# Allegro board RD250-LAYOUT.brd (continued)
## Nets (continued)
SIG007121: R301.2 R302.1
SIG007122: R302.2 R303.1
SIG007123: C302.2 D302.C D305.C DP301.1 IC301.5 R304.2 R305.2 R307.1
SIG007124: IC302.4 Q301.G R314.1 R315.2
SIG007125: Q302.D Q303.G R318.1 R319.2
SIG007126: D305.A R320.1 R321.2
SIG007127: D306.A R322.1 R323.2
SIGN254: D66.A R66.1
SIGN255: D61.A R58.1
SIGN266: C81.2 DP55.1 L54.2 Q52.G R64.2
SIGN267: C82.2 DP53.1 L53.2 Q51.G R56.2
SS/EN: C251.2 IC251.5 R252.2 R353.2
VREF_PSFB: C254.2 IC251.1 R263.2 R265.2 R268.2 R270.2 R272.2 R279.2

Pads without a net: CN2 2; CN102 1; CN105 1; D104 NC; D107 NC; D113 NC; D116 NC; D405 NC; IC1 1 4 5 8; IC101 7 12 13; IC102 7 12 13; IC151 1 8; IC201 1 8; IC251 16; IC304 7 10; IC403 4; IC451 4; T101 4 6 7; T151 1 3 4 6 7 8 9 10 11 12; T201 1 3 4 6 7 8 9 10 11 12; T401 2 7 10 11 14

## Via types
v1: diameter 7, hole 3.2, TOP to BOTTOM, 4 vias
v2: diameter 0.55, hole 0.3, TOP to BOTTOM, 659 vias

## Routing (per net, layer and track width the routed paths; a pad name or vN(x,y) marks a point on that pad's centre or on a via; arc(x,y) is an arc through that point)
P48V: length 44.3
  CONDUCTIVE3 w0.3: CN503.1 292.18,30.38 CN501.3
  CONDUCTIVE4 w0.5: CN501.4 299.15,24.7 299.15,11.3 v2(301.45,9)
  BOTTOM w0.5: C511.2 316.4,26.25 ; C511.2 317.75,25.25 ; C511.2 C510.2 ; C510.2 313.9,26.45 ; C510.2 312.35,25.25
VCC5R0_1: length 199.5
  TOP w0.3: 147.15,106.61 v2(147.15,105.25) 147.75,104.65 151.2,104.65 152.53,105.98 IC101.8 ; 184.31,60.39 184.31,61.75 ; 184.31,61.75 v2(182.8,61.75) ; 184.31,61.75 C413.2
  TOP w0.825: IC403.5 184.31,60.39
  TOP w0.92: 147.15,106.61 C104.2
  CONDUCTIVE3 w0.3: v2(220.4,11.9) 218.25,11.9 213.4,7.05 209.18,7.05 209.08,7.02 209.04,6.99 208.1,6.05 195.25,6.05 190.9,10.4 190.9,53.65 v2(182.8,61.75)
  CONDUCTIVE4 w0.3: v2(147.15,105.25) 137.75,95.85 137.75,85.15 144.55,78.35 149,78.35 158.55,68.8 179.05,68.8 182.8,65.05 v2(182.8,61.75) 181.3,61.75 179.5,63.55 179.5,66.15 v2(177.65,68)
  BOTTOM w0.3: IC304.16 222.3,11.63 222.14,11.47 C309.2 220.82,11.47 v2(220.4,11.9)
  vias: v2(167.4,67.75) v2(173.3,67.55)
VCC5R0_2: length 4.7
  BOTTOM w0.3: 235.77,13.3 236.68,13.3 ; IC304.1 233.12,12.47 233.95,13.3 235.6,13.3
  BOTTOM w0.4: 235.6,13.3 235.77,13.3
VCC12R0_1: length 31.7
  TOP w0.3: v2(144.4,53.5) 143.85,53.5 143.26,52.91 143.26,52.04 ; 142,44.3 v2(143.1,44.3) ; 220.28,6.12 221.6,6.12
  TOP w0.45: R314.2 220.28,6.12 ; 141.82,44.3 142,44.3
  TOP w0.825: IC51.8 143.26,52.04
  CONDUCTIVE4 w0.3: v2(122.5,3.4) 130.42,3.4 130.52,3.43 130.56,3.46 v2(133.6,6.5)
  BOTTOM w0.3: RY1.4 97.2,70.88 97.17,70.98 97.14,71.02 95.67,72.49 95.58,72.54 95.53,72.55 D1.C ; 206.28,6.4 204.62,4.75 v2(202.9,4.75) v2(202.1,4.75) ; 97.12,65.91 C11.2
  BOTTOM w0.45: R4.1 97.12,65.91
  vias: v2(149.25,103.5) v2(153.3,43.9) v2(184.3,52.55) v2(184.3,51.85)
VCC12R0_2:
  vias: v2(243.15,123.55) v2(243.15,85.45) v2(243.95,123.55) v2(243.95,85.45) v2(248.8,13.5) v2(258.65,28.7) v2(258.65,27.9) v2(258.65,27.1) v2(259.45,28.7) v2(259.45,27.9) v2(259.45,27.1)
ACIN: length 16.2
  BOTTOM w0.3: 122,17.43 122,19.37 121.97,19.47 121.94,19.52 120.04,21.42 119.95,21.47 119.9,21.48 R301.1 ; 113.89,21.48 110.47,21.48 110.37,21.45 110.32,21.42 D51.C
  BOTTOM w0.92: R301.1 113.89,21.48 ; C301.2 122,17.43
CONN002: length 7.9
  TOP w0.3: 150.78,90.48 150.78,91.4 ; 145.72,86 150.02,90.3 150.78,90.3
  TOP w0.45: 150.78,90.3 150.78,90.48
  vias: v2(166.15,76.15) v2(166.85,76.15)
CONN004: length 222.9
  TOP w0.3: 285.81,37.01 284.76,37.01 284.3,36.55 283.5,36.55 283,37.05 283,41.15 284.75,42.9 287.65,42.9 288.1,42.45 C509.2 ; 288.21,41.5 v2(289.6,41.5) ; 288.1,41.03 288.1,39.19
  TOP w0.8: 288.1,41.03 C509.2 288.21,41.5
  TOP w0.825: IC501.3 285.81,37.01
  CONDUCTIVE3 w0.3: v2(305.75,47.6) 305.75,48.25 305.35,48.65 296.75,48.65 v2(289.6,41.5)
  CONDUCTIVE3 w0.5: v2(267.5,14.1) 271.1,14.1 296.8,39.8 296.8,45.15 299.25,47.6 v2(305.75,47.6)
  CONDUCTIVE3 w1.5: C501.2 285.1,125.7 ; C501.2 287.3,126.95 ; C501.2 289.5,125.7 ; C501.2 287.3,123.5 ; C505.2 299.7,76.4 ; C505.2 299.7,79.85 ; C505.2 297.5,78.6 ; C505.2 301.9,78.6 ; C503.2 306.5,67.95 ; C503.2 308.7,65.75 ; C503.2 308.7,70.15 ; C503.2 310.9,67.95 ; C504.2 287.3,76 ; C504.2 287.3,79.85 ; C504.2 289.5,78.6 ; C504.2 285.1,78.6 ; C502.2 301.9,125.7 ; C502.2 299.7,123.5 ; C502.2 299.7,126.95 ; C502.2 297.5,125.7
  CONDUCTIVE4 w1.5: C505.2 299.7,79.85 ; C505.2 299.7,76.4 ; C505.2 301.9,78.6 ; C505.2 297.5,78.6 ; C504.2 287.3,79.85 ; C504.2 289.5,78.6 ; C504.2 287.3,76.05 ; C504.2 285.1,78.6 ; C501.2 285.1,125.7 ; C501.2 289.5,125.7 ; C501.2 287.3,123.5 ; C501.2 287.3,126.95 ; C502.2 299.7,123.5 ; C502.2 301.9,125.7 ; C502.2 299.7,126.95 ; C502.2 297.5,125.7 ; C503.2 308.7,65.75 ; C503.2 310.9,67.95 ; C503.2 308.7,70.15 ; C503.2 306.5,67.95
  BOTTOM w0.3: 267.5,13.1 v2(267.5,14.1)
  BOTTOM w0.45: R287.2 267.5,13.1
  BOTTOM w0.5: 284,128.15 283.25,128.9 C507.2 ; C506.2 280.65,81.8 ; C506.2 283.3,81.8 ; C506.2 282,80.9 ; C507.2 282.3,127.75 ; C507.2 280.75,128.9
  BOTTOM w1.5: C502.2 299.7,126.95 ; C502.2 297.9,125.7 ; C502.2 301.7,125.7 ; C502.2 299.7,124 ; C505.2 301.9,78.6 ; C505.2 297.5,78.6 ; C505.2 299.7,79.8 ; C505.2 299.7,76.4 ; C501.2 287.3,126.95 ; C501.2 289.6,125.7 ; C501.2 287.3,123.65 ; C501.2 285.25,125.7 ; C504.2 287.3,79.85 ; C504.2 287.3,76.05 ; C504.2 285.1,78.6 ; C504.2 289.5,78.6 ; C503.2 308.7,66.25 ; C503.2 310.9,67.95 ; C503.2 306.5,67.95 ; C503.2 308.7,70.15
  vias: v2(279.65,127.3) v2(279.65,81.2) v2(280.45,127.3) v2(280.45,81.2) v2(297.2,116.8) v2(297.2,116.1) v2(297.2,115.4) v2(297.2,114.7) v2(297.2,114) v2(297.2,113.3) v2(297.2,112.6) v2(297.2,111.9) v2(297.2,111.2) v2(297.2,110.5) v2(297.2,69.7) v2(297.2,69) v2(297.2,68.3) v2(297.2,67.6) v2(297.2,66.9) v2(297.2,66.2) v2(297.2,65.5) v2(297.2,64.8) v2(297.2,64.1) v2(297.2,63.4) v2(297.2,53.5) v2(297.2,52.8) v2(297.2,52.1) v2(297.2,51.4) v2(297.2,50.7) v2(297.2,50) v2(297.9,116.8) v2(297.9,116.1) v2(297.9,115.4) v2(297.9,114.7) v2(297.9,114) v2(297.9,113.3) v2(297.9,112.6) v2(297.9,111.9) v2(297.9,111.2) v2(297.9,110.5) v2(297.9,69.7) v2(297.9,69) v2(297.9,68.3) v2(297.9,67.6) v2(297.9,66.9) v2(297.9,66.2) v2(297.9,65.5) v2(297.9,64.8) v2(297.9,64.1) v2(297.9,63.4) v2(297.9,53.5) v2(297.9,52.8) v2(297.9,52.1) v2(297.9,51.4) v2(297.9,50.7) v2(297.9,50) v2(298.6,116.8) v2(298.6,116.1) v2(298.6,115.4) v2(298.6,114.7) v2(298.6,114) v2(298.6,113.3) v2(298.6,112.6) v2(298.6,111.9) v2(298.6,111.2) v2(298.6,110.5) v2(298.6,69.7) v2(298.6,69) v2(298.6,68.3) v2(298.6,67.6) v2(298.6,66.9) v2(298.6,66.2) v2(298.6,65.5) v2(298.6,64.8) v2(298.6,64.1) v2(298.6,63.4) v2(298.6,53.5) v2(298.6,52.8) v2(298.6,52.1) v2(298.6,51.4) v2(298.6,50.7) v2(298.6,50) v2(299.3,116.8) v2(299.3,116.1) v2(299.3,115.4) v2(299.3,114.7) v2(299.3,114) v2(299.3,113.3) v2(299.3,112.6) v2(299.3,111.9) v2(299.3,111.2) v2(299.3,110.5) v2(299.3,69.7) v2(299.3,69) v2(299.3,68.3) v2(299.3,67.6) v2(299.3,66.9) v2(299.3,66.2) v2(299.3,65.5) v2(299.3,64.8) v2(299.3,64.1) v2(299.3,63.4) v2(299.3,53.5) v2(299.3,52.8) v2(299.3,52.1) v2(299.3,51.4) v2(299.3,50.7) v2(299.3,50) v2(300,116.8) v2(300,116.1) v2(300,115.4) v2(300,114.7) v2(300,114) v2(300,113.3) v2(300,112.6) v2(300,111.9) v2(300,111.2) v2(300,110.5) v2(300,69.7) v2(300,69) v2(300,68.3) v2(300,67.6) v2(300,66.9) v2(300,66.2) v2(300,65.5) v2(300,64.8) v2(300,64.1) v2(300,63.4) v2(300,53.5) v2(300,52.8) v2(300,52.1) v2(300,51.4) v2(300,50.7) v2(300,50) v2(300.7,116.8) v2(300.7,116.1) v2(300.7,115.4) v2(300.7,114.7) v2(300.7,114) v2(300.7,113.3) v2(300.7,112.6) v2(300.7,111.9) v2(300.7,111.2) v2(300.7,110.5) v2(300.7,69.7) v2(300.7,69) v2(300.7,68.3) v2(300.7,67.6) v2(300.7,66.9) v2(300.7,66.2) v2(300.7,65.5) v2(300.7,64.8) v2(300.7,64.1) v2(300.7,63.4) v2(300.7,53.5) v2(300.7,52.8) v2(300.7,52.1) v2(300.7,51.4) v2(300.7,50.7) v2(300.7,50)
CS: length 36.6
  TOP w0.3: v2(249.7,10.9) R284.2 ; 250.12,8.8 251.6,8.8
  TOP w0.83: R284.2 250.12,8.8
  CONDUCTIVE3 w0.5: v2(249.7,10.9) 247.05,13.55 v2(247.05,42.4)
CSA: length 129.7
  TOP w0.3: D62.C 140.68,45.2 140.97,44.9 140.97,44.48 ; v2(143.8,37.4) 140.97,40.23 140.97,44.12 ; DP52.1 155.6,3.8 155,4.4 v2(154.45,4.4)
  TOP w0.45: 140.97,44.48 R59.1 140.97,44.12
  CONDUCTIVE3 w0.3: v2(154.45,4.4) 153.75,5.1 153.75,8.35 152.7,9.4 152.7,35.25 150.55,37.4 v2(143.8,37.4) 141.8,37.4 137.5,41.7 121.55,41.7 112.8,50.45 112.8,76.75 114.7,78.65 v2(114.7,82.2)
  BOTTOM w0.3: 153.58,4.35 154.45,4.35 ; D58.C 116.62,84.53 116.3,84.2 R52.2 115.37,82.5 115.07,82.2 v2(114.7,82.2)
  BOTTOM w0.45: R68.1 153.58,4.35
CSB: length 104.1
  TOP w0.3: 155.3,43.9 D67.C ; R67.1 155.12,42.95 154.18,42 v2(150.15,42) ; v2(156.2,5.4) 157.72,5.4 157.77,5.39 157.86,5.34 DP54.1
  TOP w0.45: R67.1 155.3,43.9
  CONDUCTIVE3 w0.3: v2(156.2,5.4) 157.7,6.9 157.7,34.45 v2(150.15,42) 150.15,51.2 144.9,56.45 144.9,62.95 139.2,68.65 139.2,79.2 133.5,84.9 v2(131.9,84.9)
  BOTTOM w0.3: 155.38,5.4 v2(156.2,5.4)
  BOTTOM w0.45: R69.1 155.38,5.4
FG1:
  vias: v1(58.6,58)
FG2: length 5.5
  BOTTOM w0.3: 304.55,9.97 C513.2 303.45,9.25 ; 304.55,9.97 R506.1 ; 304.55,9.97 R505.1 304.55,9.25 ; R506.1 305.65,9.2 ; R506.1 306.75,9.97
  vias: v1(311.5,7)
HS1_1: length 6.9
  TOP w0.3: 80.88,129.53 87.6,129.53
  TOP w0.45: R422.2 80.88,129.53
HS1_2: length 10.1
  BOTTOM w0.5: R423.2 176.07,124.03 v1(170.6,129.5)
LGND: length 311.2
  TOP w0.3: 249.7,7.14 v2(249.7,5.75) 249.7,4.7 ; 249.7,3.6 249.7,4.53
  TOP w0.4: 249.7,4.53 249.7,4.7
  TOP w0.5: DP501.1 299.05,21.7 ; DP501.1 295.3,21.7 ; DP501.1 297.05,20.1 ; DP501.1 297.05,23.45
  TOP w0.83: R284.1 249.7,7.14
  TOP w1.5: C501.1 287.3,132.6 ; C501.1 289.55,130.7 ; C501.1 284.85,130.7 ; C504.1 287.3,85.4 ; C504.1 287.3,82.45 ; C504.1 289.75,83.6 ; C504.1 285.45,83.6 ; C503.1 315.4,67.95 ; C503.1 313.7,66.1 ; C503.1 313.7,70.35 ; C505.1 297.35,83.6 ; C505.1 v2(299.7,85.95) ; C505.1 299.7,82.45 ; C505.1 301.5,83.6 ; C502.1 v2(299.7,133.1) ; C502.1 301.8,130.7 ; C502.1 297.85,130.7
  CONDUCTIVE2 w0.5: DP257.1 269.3,6.4 ; DP257.1 271.25,8.85 ; DP257.1 271.25,4.05 ; DP501.1 295.15,21.7 ; DP501.1 297.05,23.85 ; DP501.1 298.9,21.7 ; DP501.1 297.05,20
  CONDUCTIVE2 w1: T401.9 T401.8 236.71,18.41 236.15,17.85 236.15,14.2 237.4,12.95 C414.2
  CONDUCTIVE2 w1.5: C501.1 287.3,132.9 ; C501.1 285.1,130.7 ; C501.1 287.3,128.5 ; C501.1 289.5,130.7 ; C504.1 287.3,81.4 ; C504.1 287.3,85.8 ; C504.1 285.1,83.6 ; C504.1 289.5,83.6 ; 238.19,57.2 T101.3 240.59,54.8 ; C502.1 297.5,130.7 ; C502.1 299.7,128.5 ; C502.1 301.9,130.7 ; C502.1 299.7,132.9 ; C503.1 313.7,65.75 ; C503.1 311.5,67.95 ; C503.1 315.9,67.95 ; C503.1 313.7,70.15 ; C505.1 299.7,85.8 ; C505.1 301.9,83.6 ; C505.1 297.5,83.6 ; C505.1 299.7,81.4
  CONDUCTIVE3 w0.3: CN502.2 293.23,19.07 CN503.2
  CONDUCTIVE5 w0.5: DP501.1 298.9,21.7 ; DP501.1 295.15,21.7 ; DP501.1 297.05,20 ; DP501.1 297.05,23.85 ; DP257.1 269.3,6.4 ; DP257.1 271.25,4.05 ; DP257.1 271.25,8.85
  CONDUCTIVE5 w1: C414.2 237.4,12.95 236.15,14.2 236.15,17.85 236.71,18.41 T401.8 T401.9
  CONDUCTIVE5 w1.5: 238.19,57.2 T101.3 240.59,54.8 ; C504.1 287.3,85.8 ; C504.1 289.5,83.6 ; C504.1 285.1,83.6 ; C504.1 287.3,81.4 ; C502.1 299.7,128.5 ; C502.1 301.9,130.7 ; C502.1 297.5,130.7 ; C502.1 299.7,132.9 ; C503.1 313.7,70.15 ; C503.1 311.5,67.95 ; C503.1 313.7,65.75 ; C503.1 315.9,67.95 ; C501.1 289.5,130.7 ; C501.1 285.1,130.7 ; C501.1 287.3,128.5 ; C501.1 287.3,132.9 ; C505.1 299.7,85.8 ; C505.1 297.5,83.6 ; C505.1 301.9,83.6 ; C505.1 299.7,81.4
  BOTTOM w0.3: R208.1 265.23,87.9 ; R208.1 266,88.95 ; R208.1 265.23,89.9 ; R204.1 266.55,75.9 ; R204.1 265.68,75 ; R204.1 265.68,76.85 ; R158.1 265.23,128 ; R158.1 266.05,127.05 ; R158.1 265.23,126.05 ; 304.55,10.82 304.55,11.55 ; 304.55,10.82 305.65,10.82 ; 304.55,10.82 303.45,10.82 ; R154.1 265.68,113.05 ; R154.1 265.68,114.8 ; R154.1 266.65,113.9 ; 259.57,13.22 C254.1 v2(258.7,12.2) ; 233.72,2.42 v2(235.15,2.42) 235.73,2.42 235.85,2.3 R365.1 ; 235.78,12.47 C453.1 ; 305.65,10.82 306.6,10.82 ; 305.65,10.82 305.65,11.6 ; 238.98,12.47 242.68,12.47 ; IC304.2 234.32,10.22 235.6,11.5 235.6,12.35 ; 239.29,8.32 239.88,8.32 240.05,8.5 v2(240.55,8.5) ; 303.45,10.82 302.4,10.82 ; 303.45,10.82 303.45,11.65
  BOTTOM w0.45: R273.1 259.57,13.22 ; 239.25,8.32 239.29,8.32 ; 235.78,12.47 C351.1 235.6,12.35 ; C453.1 238.98,12.47
  BOTTOM w0.5: DP501.1 297.05,23.45 ; DP501.1 298.85,21.7 ; DP501.1 297.05,20.15 ; DP501.1 295.3,21.7 ; C511.1 317.7,23.45 ; C511.1 C510.1 ; C511.1 316.4,22.35 ; T101.3 243.54,49.45 R251.1 ; C510.1 313.9,22.4 ; C510.1 312.45,23.45 ; C507.1 283.95,130.7 ; C507.1 282.3,131.85 ; C507.1 280.75,130.7 ; C506.1 283.55,83.6 ; C506.1 280.2,83.6 ; C506.1 282,84.95
  BOTTOM w0.825: 233.12,2.42 233.72,2.42
  BOTTOM w1.5: C505.1 299.7,82.45 ; C505.1 v2(299.7,85.95) 299.7,86.05 ; C505.1 297.1,83.6 ; C505.1 300.9,83.6 ; C502.1 301.75,130.7 ; C502.1 297.3,130.7 ; C502.1 299.7,129.45 ; C502.1 v2(299.7,133.1) ; C504.1 287.3,85.3 ; C504.1 289.35,83.6 ; C504.1 285.1,83.6 ; C504.1 287.3,82.45 ; C501.1 289.1,130.7 ; C501.1 287.3,132.65 ; C501.1 287.3,129.45 ; C501.1 285.35,130.7
  vias: v2(240.55,4.8) v2(244.15,122) v2(244.15,83.9) v2(244.85,122) v2(244.85,83.9) v2(245.35,12.5) v2(247,49.4) v2(248,118.9) v2(248,80.8) v2(248.85,18.7) v2(248.85,17.9) v2(248.85,17.1) v2(248.85,16.3) v2(249.65,18.7) v2(249.65,17.9) v2(249.65,17.1) v2(249.65,16.3) v2(250.45,122) v2(250.45,83.9) v2(251.15,122) v2(251.15,83.9) v2(253.4,12.45) v2(253.4,11.65) v2(253.85,18.7) v2(253.85,17.9) v2(253.85,17.1) v2(253.85,16.3) v2(254.65,18.7) v2(254.65,17.9) v2(254.65,17.1) v2(254.65,16.3) v2(259.8,2.3) v2(261.45,84.25) v2(261.5,122.6) v2(262.35,3.3) v2(264.07,130.05) v2(264.05,112.15) v2(264.07,93.45) v2(264.05,73.55) v2(264.88,130.05) v2(264.85,112.15) v2(264.88,93.45) v2(264.85,73.55) v2(266.05,132.05) v2(266.05,131.35) v2(266.05,130.65) v2(266.05,129.95) v2(266.05,129.25) v2(266.05,128.55) v2(266.05,127.85) v2(266.15,112.45) v2(266.15,111.75) v2(266.15,111.05) v2(266.15,110.35) v2(266.15,109.65) v2(266.15,108.95) v2(266.15,108.25) v2(266.05,93.95) v2(266.05,93.25) v2(266.05,92.55) v2(266.05,91.85) v2(266.05,91.15) v2(266.05,90.45) v2(266.05,89.75) v2(266.15,74.35) v2(266.15,73.65) v2(266.15,72.95) v2(266.15,72.25) v2(266.15,71.55) v2(266.15,70.85) v2(266.15,70.15) v2(266.75,132.05) v2(266.75,131.35) v2(266.75,130.65) v2(266.75,129.95) v2(266.75,129.25) v2(266.75,128.55) v2(266.75,127.85) v2(266.75,93.95) v2(266.75,93.25) v2(266.75,92.55) v2(266.75,91.85) v2(266.75,91.15) v2(266.75,90.45) v2(266.75,89.75) v2(266.85,112.45) v2(266.85,111.75) v2(266.85,111.05) v2(266.85,110.35) v2(266.85,109.65) v2(266.85,108.95) v2(266.85,108.25) v2(266.85,74.35) v2(266.85,73.65) v2(266.85,72.95) v2(266.85,72.25) v2(266.85,71.55) v2(266.85,70.85) v2(266.85,70.15) v2(267.45,132.05) v2(267.45,131.35) v2(267.45,130.65) v2(267.45,129.95) v2(267.45,129.25) v2(267.45,93.95) v2(267.45,93.25) v2(267.45,92.55) v2(267.45,91.85) v2(267.45,91.15) v2(267.55,112.45) v2(267.55,111.75) v2(267.55,111.05) v2(267.55,110.35) v2(267.55,109.65) v2(267.55,108.95) v2(267.55,108.25) v2(267.55,74.35) v2(267.55,73.65) v2(267.55,72.95) v2(267.55,72.25) v2(267.55,71.55) v2(267.55,70.85) v2(267.55,70.15) v2(268.15,132.05) v2(268.15,131.35) v2(268.15,130.65) v2(268.15,129.95) v2(268.15,129.25) v2(268.15,93.95) v2(268.15,93.25) v2(268.15,92.55) v2(268.15,91.85) v2(268.15,91.15) v2(268.15,7.85) v2(268.25,112.45) v2(268.25,111.75) v2(268.25,111.05) v2(268.25,110.35) v2(268.25,109.65) v2(268.25,108.95) v2(268.25,108.25) v2(268.25,74.35) v2(268.25,73.65) v2(268.25,72.95) v2(268.25,72.25) v2(268.25,71.55) v2(268.25,70.85) v2(268.25,70.15) v2(268.95,112.45) v2(268.95,111.75) v2(268.95,111.05) v2(268.95,110.35) v2(268.95,109.65) v2(268.95,108.95) v2(268.95,108.25) v2(268.95,74.35) v2(268.95,73.65) v2(268.95,72.95) v2(268.95,72.25) v2(268.95,71.55) v2(268.95,70.85) v2(268.95,70.15) v2(269.65,112.45) v2(269.65,111.75) v2(269.65,111.05) v2(269.65,110.35) v2(269.65,109.65) v2(269.65,108.95) v2(269.65,108.25) v2(269.65,74.35) v2(269.65,73.65) v2(269.65,72.95) v2(269.65,72.25) v2(269.65,71.55) v2(269.65,70.85) v2(269.65,70.15) v2(270.35,112.45) v2(270.35,111.75) v2(270.35,111.05) v2(270.35,110.35) v2(270.35,109.65) v2(270.35,108.95) v2(270.35,108.25) v2(270.35,74.35) v2(270.35,73.65) v2(270.35,72.95) v2(270.35,72.25) v2(270.35,71.55) v2(270.35,70.85) v2(270.35,70.15) v2(283.6,132.4) v2(283.6,131) v2(284.25,38.5) v2(284.25,37.7) v2(284.3,133.1) v2(284.3,131.7) v2(285,132.4) v2(285.7,133.1) v2(286.4,132.4) v2(287.1,133.1) v2(287.1,88.75) v2(287.1,87.35) v2(287.1,85.95) v2(287.8,132.4) v2(287.8,88.05) v2(287.8,86.65) v2(288.5,133.1) v2(288.5,88.75) v2(288.5,87.35) v2(288.5,85.95) v2(289.2,132.4) v2(289.2,88.05) v2(289.2,86.65) v2(289.9,133.1) v2(289.9,131.7) v2(289.9,88.75) v2(289.9,87.35) v2(289.9,85.95) v2(290.6,132.4) v2(290.6,131) v2(290.6,88.05) v2(290.6,86.65) v2(291.3,133.1) v2(291.3,131.7) v2(291.3,88.75) v2(291.3,87.35) v2(291.3,85.95) v2(292,132.4) v2(292,131) v2(292,88.05) v2(292,86.65) v2(292.7,133.1) v2(292.7,131.7) v2(292.7,88.75) v2(292.7,87.35) v2(292.7,85.95) v2(293.4,132.4) v2(293.4,131) v2(293.4,88.05) v2(293.4,86.65) v2(294.1,133.1) v2(294.1,131.7) v2(294.1,88.75) v2(294.1,87.35) v2(294.1,85.95) v2(294.8,132.4) v2(294.8,131) v2(294.8,88.05) v2(294.8,86.65) v2(295.5,133.1) v2(295.5,131.7) v2(295.5,88.75) v2(295.5,87.35) v2(295.5,85.95) v2(296.2,132.4) v2(296.2,131) v2(296.2,88.05) v2(296.2,86.65) v2(296.9,133.1) v2(296.9,131.7) v2(296.9,88.75) v2(296.9,87.35) v2(296.9,85.95) v2(297.6,132.4) v2(297.6,88.05) v2(297.6,86.65) v2(298.3,133.1) v2(298.3,88.75) v2(298.3,87.35) v2(298.3,85.95) v2(299,132.4) v2(299,88.05) v2(299,86.65) v2(299.7,88.75) v2(299.7,87.35) v2(300.4,132.4) v2(301.1,133.1) v2(301.8,132.4) v2(302.5,133.1) v2(302.5,131.7) v2(303.2,132.4) v2(303.2,131) v2(303.9,133.1) v2(303.9,131.7) v2(304.6,132.4) v2(304.6,131) v2(315.95,68.4) v2(315.95,67) v2(316.65,69.1) v2(316.65,67.7) v2(316.65,66.3) v2(316.65,64.9) v2(316.65,63.5) v2(316.65,62.1) v2(316.65,60.7) v2(316.65,59.3) v2(316.65,57.9) v2(316.65,56.5) v2(316.65,55.1) v2(316.65,53.7) v2(316.65,52.3) v2(316.65,50.9)
Net_1:
  vias: v1(311.5,128)
OUTA1: length 178.1
  TOP w0.3: 142.35,107.8 142.35,107.2 143.35,106.2 v2(145.6,106.2)
  TOP w0.45: R104.2 142.35,107.8
  CONDUCTIVE3 w0.3: v2(145.6,106.2) 143.6,106.2 138.7,101.3 138.7,85.4 144.85,79.25 148.95,79.25 158.15,70.05 170.05,70.05 170.45,69.65 174.1,69.65 176.1,67.65 176.1,66.35 189.6,52.85 189.6,8.1 v2(193.8,3.9)
  BOTTOM w0.3: IC304.14 222.21,8.96 215.9,2.65 195.05,2.65 v2(193.8,3.9)
OUTA2: length 17.4
  TOP w0.3: v2(244.3,7.4) 244.8,6.9 246.95,6.9
  BOTTOM w0.3: 241.4,7.4 v2(244.3,7.4) 244.66,7.4 246.94,9.68 IC251.22
  BOTTOM w0.45: 241.22,7.4 241.4,7.4
OUTB1: length 179.3
  TOP w0.3: 145.6,107.95 v2(145.6,107.15)
  TOP w0.45: 145.6,107.97 145.6,107.95
  CONDUCTIVE3 w0.3: v2(145.6,107.15) 145.6,107.9 144.95,108.55 143.6,108.55 137.85,102.8 137.85,85.1 144.6,78.35 149,78.35 157.9,69.45 169.45,69.45 170.1,68.8 173.95,68.8 175,67.75 175,66.3 188.7,52.6 188.7,7.8 v2(192.65,3.85)
  BOTTOM w0.3: v2(192.65,3.85) 194.45,2.05 216.35,2.05 221.99,7.68 222.92,7.68
  BOTTOM w0.55: IC304.13 222.92,7.68
OUTB2: length 31.9
  TOP w0.3: v2(256.4,9.5) 257.25,9.5 259.95,12.2 259.95,14.05 263.3,17.4 DP252.1
  BOTTOM w0.3: 255.43,9.03 255.93,9.03 v2(256.4,9.5) ; 241.4,5.9 244.08,5.9 247.21,9.03 IC251.21
  BOTTOM w0.4: IC251.21 255.43,9.03
  BOTTOM w0.45: 241.22,5.9 241.4,5.9
OUTC1: length 117.6
  TOP w0.3: v2(169.95,65.25) 169.7,65 164.15,65 162.95,66.2 162.95,66.97
  TOP w0.45: R115.2 162.95,66.97
  CONDUCTIVE3 w0.3: v2(169.95,65.25) 170.25,64.95 173.6,64.95 183.55,55 183.55,54.25 184.5,53.3 185.25,53.3 187.15,51.4 187.15,6.1 v2(190.15,3.1)
  BOTTOM w0.3: v2(190.15,3.1) 192,3.1 193.65,1.45 216.8,1.45 221.76,6.42 222.86,6.42
  BOTTOM w0.55: IC304.12 222.86,6.42
OUTC2: length 32.4
  TOP w0.3: DP253.1 264.25,16.5 260.9,13.15 260.9,11.9 257.35,8.35 v2(256.4,8.35)
  BOTTOM w0.3: IC251.20 247.47,8.38 242.55,3.45 241.4,3.45 ; 255.43,8.38 256.38,8.38
  BOTTOM w0.4: IC251.20 255.43,8.38
  BOTTOM w0.45: 241.22,3.45 241.4,3.45
OUTD1: length 113.9
  TOP w0.3: R114.2 167,65.67 167.17,65.85 v2(169.2,65.85)
  CONDUCTIVE3 w0.3: v2(191.8,2.15) 191.8,3.05 187.9,6.95 187.9,51.85 185.8,53.95 185.1,53.95 184.3,54.75 184.3,55.45 173.35,66.4 169.75,66.4 v2(169.2,65.85)
  BOTTOM w0.3: 222.86,5.14 221.5,5.14 217.2,0.85 193.1,0.85 v2(191.8,2.15)
  BOTTOM w0.55: IC304.11 222.86,5.14
OUTD2: length 21.3
  TOP w0.3: 246.95,2.7 245.5,2.7 244.6,3.6 v2(244.6,4.4)
  BOTTOM w0.3: 254.84,7.72 247.93,7.72 v2(244.6,4.4) 242.5,2.3 239.45,2.3
  BOTTOM w0.45: R364.2 239.45,2.3
OUTE: length 140.3
  TOP w0.3: v2(270.1,20.7) 270.1,19.75 271.4,18.45 DP255.1
  CONDUCTIVE4 w0.3: v2(258.15,7.2) 260.2,9.25 260.2,11.05 265.3,16.15 266.6,16.15 270.1,19.65 v2(270.1,20.7) 270.1,30.15 243.45,56.8 v2(243.45,78.55) 243.45,79.95 246.35,82.85 246.35,85.7 243.45,88.6 v2(243.45,116.4)
  BOTTOM w0.3: v2(243.45,78.55) 244.35,79.45 244.92,79.45 ; 255.43,7.08 256.18,7.08 256.3,7.2 v2(258.15,7.2) ; R164.1 243.95,117.55 243.45,117.05 v2(243.45,116.4)
  BOTTOM w0.4: IC251.18 255.43,7.08
  BOTTOM w0.45: R214.1 244.92,79.45
OUTF: length 146.9
  TOP w0.3: v2(268.95,22.05) 268.95,23.68 269.87,24.6 DP256.1
  CONDUCTIVE4 w0.3: v2(242.55,117.35) 242.55,88.2 245.75,85 245.75,83.35 242.55,80.15 v2(242.55,79.25) 242.55,56.4 268.95,30 v2(268.95,22.05) 268.95,19.5 266.25,16.8 265,16.8 259.55,11.35 259.55,9.95 256.55,6.95 v2(256.55,6.42)
  BOTTOM w0.3: v2(242.55,79.25) 242.55,80.6 244.1,82.15 R215.1 ; v2(242.55,117.35) 242.55,118.7 244.1,120.25 R165.1 ; 255.6,6.42 v2(256.55,6.42)
  BOTTOM w0.4: 254.84,6.42 255.6,6.42
PFC_OFF: length 2.2
  BOTTOM w0.3: 136.71,11.9 DP61.1
  BOTTOM w0.45: R308.1 136.71,11.9
PFC_OUT: length 31.5
  TOP w0.3: DP51.1 v2(173.5,5.75)
  CONDUCTIVE3 w0.3: C52.2 173.5,21.7 v2(173.5,5.75)
PN: length 621.3
  TOP w0.3: 122.3,8.82 122.92,9.44 122.96,9.47 123.06,9.5 v2(124.5,9.5) v2(125.5,9.5) v2(126.5,9.5) v2(127.5,9.5) ; 151.89,55.05 148.97,55.05 148.66,55.37 Q52.S ; Q51.S 117.46,52 119.56,49.9 122.8,49.9 ; 185.22,55.95 185.22,56.4 185.4,56.58 185.4,57.32 ; C413.1 185.4,61.52 IC403.2 ; v2(170.95,65.65) 170.95,64.8 170.5,64.35 163.85,64.35 161.85,66.35 161.85,66.87 ; 158.07,127.22 R113.1 ; Q102.S 158.84,127.4 158.25,127.4 ; R82.1 150.8,2.9 v2(149.8,1.9) ; v2(80.7,127.2) 80.7,128.68 ; v2(161.2,47.15) 161.78,47.15 162.03,47.4 C61.1 ; v2(185.25,55.05) 185.25,56 ; v2(131.15,47.7) C59.1 ; 152.07,54.13 C81.1 ; 122.97,49.72 R56.1
  TOP w0.45: C113.1 161.85,66.87 ; 122.8,49.9 C82.1 122.97,49.72 ; 158.25,127.4 C110.1 158.07,127.22 ; R64.1 152.07,54.13 ; C81.1 151.89,55.05
  TOP w0.5: T401.4 215.3,23.45 213.85,24.9 213.85,40.42 210.25,44.02 C408.1
  TOP w0.55: IC403.2 185.4,57.32
  CONDUCTIVE2 w0.3: v2(80.7,127.2) 81.58,126.33 ; v2(92.15,65.45) 94.64,62.96 94.78,62.9 v2(95.35,62.9)
  CONDUCTIVE2 w0.5: C401.1 195.45,21.45 ; C401.1 193.1,23.15 ; C401.1 190.75,21.45 ; C401.1 193.1,19.45 ; DP59.1 136.4,4.3 ; DP59.1 138.05,2.7 ; DP59.1 136.4,1.15
  CONDUCTIVE2 w1: C414.1 218.4,10.9 218.4,12.1 220.85,14.55 220.85,21.1 T401.4
  CONDUCTIVE2 w1.5: DP1.1 166.7,7.15 ; DP1.1 166.7,3.69 ; DP1.1 165.23,5 ; DP1.1 168.32,5 ; Q51.S 115.21,60.7 ; Q51.S 117.46,62.95 ; Q51.S 117.46,58.45 ; Q51.S 118.7,60.7 ; Q52.S 148.66,62.95 ; Q52.S 148.66,58.45 ; Q52.S 146.41,60.7 ; Q52.S 149.95,60.7 ; D55.4 121.9,133.07 ; D55.4 121.9,129.3 ; D55.4 119.55,131.65 ; D55.4 124.25,131.65 ; 180.5,119.65 D109.A 178.31,121.7 ; HS1.1 183.04,106.6 ; HS1.1 185.16,104 ; HS1.1 183.04,102.15 ; HS1.1 180.44,104 ; HS2.1 183.04,117.85 ; HS2.1 180.39,115.2 ; HS2.1 183.04,112.55 ; C52.1 164.7,16.75 ; C52.1 164.7,23.7 ; C52.1 168.54,20.5 ; C52.1 160.86,20.5 ; C51.1 132.74,20.7 ; C51.1 125.06,20.7 ; C51.1 128.9,16.86 ; C51.1 128.9,23.95
  CONDUCTIVE3 w0.3: v2(153.6,2.55) 153.1,3.05 153.1,7.95 151.75,9.3 151.75,34.55 150.3,36 141.8,36 136.95,40.85 121,40.85 111.85,50 111.85,77.7 113.1,78.95 v2(113.1,81.9) ; v2(197.3,16.9) 197.3,12.4 201.55,8.15 208.35,8.15 v2(209.35,9.15) ; v2(154.6,6.3) 155.15,5.75 155.4,5.75 156.9,7.25 156.9,33.8 149.15,41.55 149.15,51.1 143.75,56.5 143.75,62.8 138.55,68 138.55,78.85 133.45,83.95 130.85,83.95 v2(130,84.8)
  CONDUCTIVE5 w0.3: v2(92.15,65.45) 94.64,62.96 94.78,62.9 v2(95.35,62.9) ; v2(80.7,127.2) 81.78,126.12
  CONDUCTIVE5 w0.5: C401.1 193.1,19.45 ; C401.1 193.1,23.15 ; C401.1 190.75,21.45 ; C401.1 195.45,21.45 ; DP59.1 136.4,1.15 ; DP59.1 136.4,4.3 ; DP59.1 138.05,2.7
  CONDUCTIVE5 w1: C414.1 218.4,10.9 218.4,12.1 220.85,14.55 220.85,21.1 T401.4
  CONDUCTIVE5 w1.5: HS1.1 185.16,104 ; HS1.1 180.44,104 ; HS1.1 183.04,106.6 ; HS1.1 183.04,102.15 ; HS2.1 180.39,115.2 ; HS2.1 183.04,117.85 ; HS2.1 183.04,112.55 ; C51.1 128.9,16.86 ; C51.1 132.74,20.7 ; C51.1 128.9,23.95 ; C51.1 125.06,20.7 ; Q51.S 115.21,60.7 ; Q51.S 117.46,62.95 ; Q51.S 118.7,60.7 ; Q51.S 117.46,58.45 ; C52.1 164.7,16.75 ; C52.1 168.54,20.5 ; C52.1 160.86,20.5 ; C52.1 164.7,23.7 ; DP1.1 166.7,7.15 ; DP1.1 166.7,3.69 ; DP1.1 165.23,5 ; DP1.1 168.32,5 ; D55.4 119.55,131.65 ; D55.4 124.25,131.65 ; D55.4 121.9,133.07 ; D55.4 121.9,129.3 ; Q52.S 148.66,58.45 ; Q52.S 148.66,62.95 ; Q52.S 146.41,60.7 ; Q52.S 149.95,60.7 ; 180.5,119.65 D109.A 178.31,121.7
  BOTTOM w0.3: 141.38,14.32 142.4,14.32 ; R60.1 129.14,85.66 v2(130,84.8) 130,84.17 130.68,83.5 130.68,82.72 131.1,82.3 132.65,82.3 139.2,75.75 139.2,70.5 T52.2 ; 139.6,9.45 141.05,9.45 141.3,9.2 C68.1 142.3,8.62 142.5,8.43 143.28,8.43 ; T51.2 114.1,68.1 113.1,69.1 113.1,80.88 ; 113.1,80.88 C58.1 ; 113.1,80.88 v2(113.1,81.9) 112.65,82.35 R52.1 ; 142.58,14.32 143.9,14.32 ; v2(137.85,73.9) 137.85,75.58 ; v2(95.35,62.9) C11.1 ; 169.82,90.3 R124.1
  BOTTOM w0.4: IC52.16 143.28,8.43
  BOTTOM w0.45: C121.1 169.82,90.3 ; 142.4,14.32 142.58,14.32 ; 141.2,14.32 141.38,14.32
  BOTTOM w0.5: T401.4 213.15,18.1 208.45,18.1 207.95,17.6 C405.1
  vias: v2(132.9,4.65) v2(134.8,9.8) v2(135.6,9.8) v2(140.65,2.75) v2(144.55,107.15) v2(144.8,14.45) v2(145.4,8.4) v2(145.55,48.1) v2(145.6,14.45) v2(145.8,1.9) v2(146.2,8.4) v2(146.35,48.1) v2(147.8,1.9) v2(149.25,108.65) v2(149.25,105.5) v2(149.5,39.6) v2(149.95,108.65) v2(149.95,105.5) v2(150.65,108.65) v2(150.65,105.5) v2(153.6,117.8) v2(153.6,117.1) v2(154,12.85) v2(154,12.05) v2(154,11.25) v2(155.35,6.95) v2(155.5,116.35) v2(156.2,116.35) v2(171.65,65.65) v2(174.4,74.8) v2(174.4,74.1) v2(177.65,66.5) v2(177.65,65.8) v2(178.55,76.05) v2(178.55,75.35) v2(179.5,54.9) v2(185.45,47.75) v2(185.45,46.95) v2(211,5.3) v2(211,4.6) v2(221.15,9.8) v2(221.45,1.8) v2(222.15,1.8)
RY_OFF: length 73.9
  CONDUCTIVE4 w0.3: v2(130.95,6.5) 130.95,8.77 130.92,8.87 130.89,8.91 123.91,15.89 123.88,15.93 123.85,16.03 123.85,22.27 123.82,22.37 123.79,22.41 113.56,32.64 113.53,32.68 113.5,32.78 113.5,41.42 113.47,41.52 113.44,41.56 102.81,52.19 102.78,52.23 102.75,52.33 102.75,60.12 102.72,60.22 102.69,60.26 97.71,65.24 97.62,65.29 97.57,65.3 v2(96.25,65.3)
SIG1: length 19.6
  BOTTOM w0.3: R1.2 45.62,29.86 45.52,29.84 45.48,29.8 L1.1
  BOTTOM w0.5: C2.2 42.3,60.7 37.05,55.45 F1.2
SIG2: length 77.5
  CONDUCTIVE3 w0.5: CN2.3 22.58,21.37 20.5,23.45 CN1.3 34.75,34.1 RV1.2
  BOTTOM w0.3: R2.1 46.76,12.94 46.71,12.94 46.62,13 L1.4
  BOTTOM w0.5: RV1.2 45.15,53.35 C3.2
SIG6: length 26.4
  BOTTOM w0.3: D54.A 98.17,13.63 98.14,13.68 98.11,13.78 L2.3 100.86,18.17 100.92,18.21 D52.A
  BOTTOM w0.5: C8.2 64.3,77.5 C9.1
SIG8: length 130.3
  CONDUCTIVE3 w5: L51.1 106.7,129.3 106.7,131.65
  CONDUCTIVE4 w0.3: RY1.2 89.7,40.86 89.73,40.76 89.76,40.72 92.98,37.5 93.07,37.45 93.12,37.44 99.2,37.44 99.25,37.43 99.34,37.38 108.82,27.9 108.85,27.86 108.88,27.76 v2(108.88,14.7)
  CONDUCTIVE4 w5: L51.1 106.7,129.3 106.7,131.65
  BOTTOM w0.3: v2(108.88,14.7) 109.24,15.06 109.3,15.2 D51.A
SIG11: length 42.3
  BOTTOM w3.5: L52.2 130.5,98.95 139.65,89.8 139.65,83.7 142.75,80.6 143.8,80.6 148.6,75.8 148.6,74.88
SIG0012: length 35.4
  CONDUCTIVE3 w0.3: R3.1 81.58,56.93 81.56,57.03 81.53,57.07 79.4,59.2
  CONDUCTIVE3 w0.5: 79.4,59.2 69.1,69.5 C7.2
SIG0013: length 13.4
  BOTTOM w0.3: 92.14,72.55 91.38,72.55 91.28,72.52 91.24,72.49 89.76,71.01 89.71,70.92 89.7,70.87 RY1.1 ; RY1.1 92.72,68.55 92.77,68.54 92.86,68.49 Q1.D ; RY1.1 89.7,66.16 89.73,66.06 89.76,66.02 R6.2
  BOTTOM w0.4: D1.A 92.14,72.55
SIG15: length 13.4
  BOTTOM w0.3: 133.72,83.5 133.72,83.17 T52.1 ; 133.72,83.68 133.72,85.47
  BOTTOM w0.45: 133.72,83.5 133.72,83.68
SIG16: length 1.3
  BOTTOM w0.3: 131.7,83.5 R61.1
  BOTTOM w0.45: C60.2 131.7,83.5
SIG20: length 7.8
  BOTTOM w0.3: 116.53,80.12 116.53,78.53 115.9,77.9 T51.1 ; R53.2 117.31,81.08 D58.A
  BOTTOM w0.45: R53.2 116.53,80.12
SIG21: length 1.1
  BOTTOM w0.3: 114.7,80.3 R53.1
  BOTTOM w0.45: C58.2 114.7,80.3
SIG0022: length 3.5
  TOP w0.3: 144.66,45.62 144.66,44.26 ; 144.68,44.12 144.68,42.98
  TOP w0.45: 144.68,44.3 144.68,44.12
  TOP w0.55: 144.66,46.44 144.66,45.62
SIG0023: length 3.5
  TOP w0.3: 147.32,44.12 147.32,42.98 ; 147.34,45.77 147.34,44.27
  TOP w0.45: 147.32,44.3 147.32,44.12
  TOP w0.825: IC51.4 147.34,45.77
SIG24: length 6.2
  TOP w0.3: 160.2,48.5 161.18,48.5 ; 159.03,44.01 159.03,44.88 160.03,45.88 R65.2 160.03,48.32
  TOP w0.45: 160.2,48.5 R66.2 160.03,48.32
  TOP w0.55: D67.A 159.03,44.01
SIG0024: length 2
  BOTTOM w0.3: 147.9,13.65 147.9,14.82 R91.2
  BOTTOM w0.45: C76.1 147.9,13.65
SIG25: length 6.3
  TOP w0.3: R57.2 133.97,45.5 134.28,45.2 136.27,45.2 ; 133.81,47.7 C59.2 ; 133.97,46.48 R58.2
  TOP w0.45: R57.2 133.97,46.48 ; R58.2 133.81,47.7
  TOP w0.55: D62.A 136.27,45.2
SIG0025: length 1
  BOTTOM w0.3: 140.84,1.7 141.68,1.7
  BOTTOM w0.45: 140.72,1.7 140.84,1.7
SIG0026: length 6.7
  BOTTOM w0.3: 141.62,5.53 R86.2 140.03,5.53 139.6,5.1 C70.2 ; R87.2 141.8,6.1 142.18,6.47 143.34,6.47
  BOTTOM w0.4: IC52.13 143.34,6.47
  BOTTOM w0.45: R87.2 141.62,5.53
SIG0027: length 5.1
  BOTTOM w0.3: C67.2 140.8,6.8 141.3,7.3 141.3,7.78 143.28,7.78
  BOTTOM w0.4: 143.97,7.78 143.28,7.78
SIG0028: length 0.9
  BOTTOM w0.3: 142.4,13.36 R83.1
  BOTTOM w0.45: R84.2 142.4,13.36
SIG0029: length 2.6
  BOTTOM w0.3: 142.4,11.59 142.4,10.78 142.8,10.38 IC52.19
  BOTTOM w0.45: 142.4,11.68 142.4,11.59
SIG30: length 5
  TOP w0.3: 135,46.3 138.12,46.3 138.93,47.1 D61.C
  TOP w0.45: 134.82,46.3 135,46.3
SIG0057: length 7.3
  BOTTOM w0.3: 261.32,10.32 262.27,10.32 263.05,11.1 263.05,12.68 262.7,13.03 R272.1 261.52,13.4 R273.2
  BOTTOM w0.4: IC251.2 261.32,10.32
SIG0058: length 1
  BOTTOM w0.3: 266.32,8.55 266.32,9.43
  BOTTOM w0.45: C256.1 266.32,8.55
SIG0059: length 8.9
  BOTTOM w0.3: 265.02,10.28 263.38,10.28 262.77,9.68 IC251.3 ; 268.7,10.22 269.52,10.22 C258.1 ; 267.32,10.28 R286.2 ; 266.22,10.28 C257.1
  BOTTOM w0.45: 268.6,10.22 268.7,10.22 ; R286.2 266.22,10.28 ; C257.1 265.02,10.28 ; 267.5,10.28 267.32,10.28
SIG102: length 5.1
  TOP w0.3: 159,47 155.9,47 155.07,47.83 D66.C
  TOP w0.45: 159.18,47 159,47
SIG115: length 4.6
  TOP w0.5: 258.95,68.11 258.95,72.4
  TOP w0.8: C204.2 258.95,68.11
SIG122: length 2.5
  TOP w0.3: 286.18,39.44 286.18,41.7
  TOP w0.825: IC501.1 286.18,39.44
SIG136: length 2.3
  TOP w0.3: 289.03,38.1 R504.1
  TOP w0.55: IC501.5 289.03,38.1
SIG141: length 23.3
  TOP w0.3: 292.25,37.59 DP502.1
  TOP w0.83: R504.2 292.25,37.59
  CONDUCTIVE3 w0.5: v2(316.5,46.25) v2(309.8,46.25) 301.3,46.25 v2(298.05,43)
SIG193: length 75.8
  TOP w5: CN1.1 20.5,53.25 29.7,62.45 F1.1
  CONDUCTIVE4 w0.5: CN1.1 15.95,43.55 15.95,29.15 30.5,14.6 CN2.1
SIG200: length 28.2
  CONDUCTIVE2 w0.5: L1.3 56.7,22.91 C5.2
SIG00211: length 17.8
  TOP w0.3: v2(161.8,4.9) 161.41,4.51 161.4,4.48 DP56.1
  BOTTOM w0.3: 157.18,8.72 158.78,8.72 160,7.5 R72.1 ; 156.82,8.72 155.8,8.72 ; v2(161.8,4.9) 160.05,4.9 ; 149.82,8.43 151.72,8.43 152.03,8.72 155.71,8.72
  BOTTOM w0.45: 155.71,8.72 155.8,8.72 ; 157.18,8.72 156.82,8.72
SIG00212: length 1
  BOTTOM w0.3: 152.4,10.43 152.4,11.3
  BOTTOM w0.45: R95.1 152.4,10.43
SIG00213: length 4.5
  TOP w0.3: v2(152.3,7) 151.15,7 150.8,6.65 R81.2
  BOTTOM w0.3: 149.82,7.12 151.6,7.12 151.72,7 v2(152.3,7)
SIG00214: length 11.6
  TOP w0.3: DP60.1 158.8,9.4 158.35,9.85 v2(156.1,9.85)
  BOTTOM w0.3: 152.58,9.43 C77.2 ; 150.48,9.07 151.2,9.07 151.55,9.43 R95.2 ; v2(156.1,9.85) 155.68,9.43 153.62,9.43
  BOTTOM w0.4: 149.82,9.07 150.48,9.07
  BOTTOM w0.45: R95.2 152.58,9.43 ; C77.2 153.62,9.43
SIG00215: length 0.9
  TOP w0.3: 150.8,4.64 R81.1
  TOP w0.45: R82.2 150.8,4.64
SIG00217: length 1
  BOTTOM w0.3: 157.03,7 157.03,7.88
  BOTTOM w0.45: R74.2 157.03,7
SIG00219: length 11.2
  CONDUCTIVE3 w0.3: v2(140.7,3.8) v2(148.7,3.8)
  BOTTOM w0.3: 149.82,4.94 149.82,3.85 ; 140.88,4.67 R87.1 ; 140.7,4.6 v2(140.7,3.8)
  BOTTOM w0.45: 140.88,4.67 R86.1 140.7,4.6
  BOTTOM w0.6: 149.82,5.08 149.82,4.94
SIG00220: length 5.4
  BOTTOM w0.3: 142.53,1.88 C73.2 ; IC52.12 142.9,5.83 142.7,5.62 142.7,3.8 142.53,3.62 142.53,2.9
  BOTTOM w0.45: C74.2 142.53,1.88 ; C73.2 142.53,2.9
SIG00221: length 2.5
  BOTTOM w0.3: 145.02,3.83 C72.2 144,4.1 143.97,4.12 143.97,5.08
  BOTTOM w0.45: C71.2 145.02,3.83
SIG00222: length 50.5
  CONDUCTIVE4 w0.3: v2(158.05,2.15) 157,1.1 122.55,1.1 118.1,5.55 v2(114.35,5.55)
  BOTTOM w0.3: v2(158.05,2.15) R72.2 ; v2(114.35,5.55) R71.1
SIG00223: length 4.7
  BOTTOM w0.3: 150.46,7.78 152.18,7.78 152.43,8.03 R79.2 ; 153.57,8.03 154.4,8.03
  BOTTOM w0.4: 149.82,7.78 150.46,7.78
  BOTTOM w0.45: R79.2 153.57,8.03
SIG00224: length 2.4
  BOTTOM w0.3: IC52.20 143.97,12.2 144.35,12.57 144.92,12.57
  BOTTOM w0.45: R77.2 144.92,12.57
SIG00225: length 5.1
  BOTTOM w0.3: 153.37,5.4 152.4,5.4 151.32,6.47 149.82,6.47 ; 153.56,5.38 154.45,5.38
  BOTTOM w0.4: 153.4,5.4 153.37,5.4
  BOTTOM w0.45: C63.2 153.56,5.38
SIG00226: length 4.1
  BOTTOM w0.3: 149.82,11.12 149.82,12.08 149.83,12.13 149.88,12.22 151.1,13.44 151.15,13.47 151.25,13.5 C65.2
SIG00228: length 4.1
  BOTTOM w0.3: 149.82,10.38 151.1,10.38 151.4,10.68 151.4,11.9 151.9,12.4 152.35,12.4
  BOTTOM w0.45: R76.2 152.35,12.4
SIG00229: length 4.4
  BOTTOM w0.3: 149.13,9.72 148.68,9.72 147.9,10.5 147.9,12.68
  BOTTOM w0.4: 149.82,9.72 149.13,9.72
SIG00230: length 1
  BOTTOM w0.3: 144,2.86 R89.2
  BOTTOM w0.45: C72.1 144,2.86
SIG00231: length 4.4
  BOTTOM w0.3: 149.82,5.83 150.57,5.83 151.5,4.9 152.03,4.9 R68.2 ; 152.57,4.2 152.57,3.33
  BOTTOM w0.45: R68.2 152.57,4.2
SIG00233: length 6.5
  TOP w0.3: v2(147.32,40.85) 147.32,42.12
  CONDUCTIVE4 w0.3: v2(145.85,9.9) 146.8,10.85 ; v2(147.32,40.85) 147.32,39.15
  BOTTOM w0.3: v2(145.85,9.9) 145.03,9.07 IC52.17
SIG00234: length 5.2
  TOP w0.3: v2(144.68,40.85) 144.68,42.12
  CONDUCTIVE4 w0.3: v2(144.68,40.85) 145.8,39.73 ; v2(145.85,7.1) 145.45,7.1
  BOTTOM w0.3: v2(145.85,7.1) 145,7.1 144.97,7.12 144.5,7.12
  BOTTOM w0.4: IC52.14 144.5,7.12
SIG00331: length 4.6
  BOTTOM w0.5: 177.3,23.23 177.3,19
  BOTTOM w1.405: R101.1 177.3,23.23
SIG00333: length 2.9
  TOP w0.3: 154.95,121.9 152.3,121.9
  TOP w1.1: 152.3,121.9 D106.C
SIG00334:
  vias: v2(142.2,117.8) v2(142.2,117.1)
SIG00336:
  vias: v2(149.85,119.75) v2(149.85,119.05)
SIG00337: length 2.5
  TOP w0.5: 149.9,123.84 R111.1
  TOP w1.1: D105.C 149.9,123.84
SIG00338: length 2
  TOP w0.5: 152,125.44 D106.A
  TOP w0.83: R112.1 152,125.44
SIG00340: length 1.8
  TOP w0.5: 137.64,124.45 D103.A
  TOP w0.83: R109.1 137.64,124.45
SIG00341: length 2.4
  TOP w0.5: 137.71,122.35 D102.C
  TOP w0.83: R108.1 137.71,122.35
SIG00342: length 14.5
  TOP w0.3: 157.05,127.4 156.76,127.4 Q102.G ; 157.22,126.48 C110.2
  TOP w0.45: R113.2 157.22,126.48 ; C110.2 157.05,127.4
  TOP w0.5: 150.42,127.35 R112.2 ; Q102.G 152.36,129.11 152,128.75 152,127.49
  TOP w0.83: R112.2 152,127.49 ; R111.2 150.42,127.35
SIG00344: length 2.2
  TOP w0.5: 159.01,76.9 D111.C
  TOP w0.83: R119.1 159.01,76.9
SIG00345:
  vias: v2(162.5,74.8) v2(162.5,74.1)
SIG00348: length 3
  TOP w0.3: IC102.6 170.66,67.94 170.85,67.74 R116.1 171.77,67.33
  TOP w0.45: C114.2 171.77,67.33
SIG00349: length 2.4
  TOP w0.5: 174.54,79.7 R122.1
  TOP w1.1: D114.C 174.54,79.7
SIG00350: length 2
  TOP w0.5: 174.76,77.6 R123.1
  TOP w0.8: D115.A 174.76,77.6
SIG00351: length 17.2
  TOP w0.3: 156.6,86 152.3,90.3 C120.2 151.62,91.22
  TOP w0.45: R121.2 151.62,91.22
  TOP w0.5: 157.1,77.44 R120.2 157.1,82.65 156.6,83.15 156.6,86
  TOP w0.83: R119.2 157.1,77.44
SIG00352: length 18.2
  TOP w0.5: 175.5,86 178,83.5 178,80.27 ; 178,78.12 R122.2
  TOP w0.83: R123.2 178,78.12 ; R122.2 178,80.27
  BOTTOM w0.3: 170.68,91.05 C121.2 ; 170.85,90.12 173.38,90.12 175.5,88 175.5,86
  BOTTOM w0.45: C121.2 170.85,90.12 ; R124.2 170.68,91.05
SIG00353:
  vias: v2(169.95,75.95) v2(170.65,75.95)
SIG00355: length 1.7
  TOP w0.5: 158.86,79.05 D112.A
  TOP w0.83: R120.1 158.86,79.05
SIG00356: length 18
  TOP w0.3: 139.47,127.17 R110.2 ; C109.2 138.91,127.35 Q101.G
  TOP w0.45: C109.2 139.47,127.17
  TOP w0.5: 135.8,123.93 R108.2 ; 135.8,125.02 135.8,126.91 134.46,128.25 Q101.G
  TOP w0.83: 135.8,123.93 R109.2 135.8,125.02
SIG00357: length 3.1
  TOP w0.3: 149.85,111.57 149.85,110.43 ; 150.03,110.42 C103.2
  TOP w0.45: R105.1 150.03,110.42
  TOP w0.55: IC101.6 149.85,111.57
SIG00362: length 8
  TOP w0.3: Q101.S 140.89,127.35 140.32,127.35 ; 140.32,127.17 140.32,126.25
  TOP w0.45: 140.32,127.35 140.32,127.17
  vias: v2(145.35,120.25) v2(146.05,120.25)
SIG00430: length 1.9
  BOTTOM w0.5: 259.5,116.17 R152.1
  BOTTOM w1.1: D151.C 259.5,116.17
SIG00431: length 1.4
  BOTTOM w0.5: 259.69,114.1 R153.1
  BOTTOM w0.8: D152.A 259.69,114.1
SIG00432: length 2.2
  BOTTOM w0.5: 259.52,127.2 R156.1
  BOTTOM w1.1: D154.C 259.52,127.2
SIG00433: length 1.7
  BOTTOM w0.5: 259.83,125.1 R157.1
  BOTTOM w0.8: D156.A 259.83,125.1
SIG00434: length 1.9
  BOTTOM w0.5: 259.5,78.08 R202.1
  BOTTOM w1.1: D201.C 259.5,78.08
SIG00435: length 1.4
  BOTTOM w0.5: 259.69,76 R203.1
  BOTTOM w0.8: D202.A 259.69,76
SIG00436: length 2.2
  BOTTOM w0.5: 259.52,89.1 R206.1
  BOTTOM w1.1: D204.C 259.52,89.1
SIG00437: length 1.7
  BOTTOM w0.5: 259.83,87 R207.1
  BOTTOM w0.8: D206.A 259.83,87
SIG00439:
  vias: v2(264.05,128.6) v2(264.05,127.9) v2(264.35,133.7) v2(265.05,133.7)
SIG00440:
  vias: v2(264.05,90.5) v2(264.05,89.8) v2(264.35,95.6) v2(265.05,95.6)
SIG00441: length 2.8
  TOP w0.5: 259.48,104.1 R155.2
  TOP w0.8: C154.1 259.48,104.1
SIG00442: length 2.7
  TOP w0.5: 257.18,126.35 259.4,126.35
  TOP w0.8: C155.1 257.18,126.35
SIG00443: length 2.7
  TOP w0.5: 257.18,88.25 259.4,88.25
  TOP w0.8: C205.1 257.18,88.25
SIG00444: length 2.8
  TOP w0.5: 259.48,66 R205.2
  TOP w0.8: C204.1 259.48,66
SIG00447: length 4.6
  TOP w0.5: 258.95,106.21 258.95,110.5
  TOP w0.8: C154.2 258.95,106.21
SIG00449:
  vias: v2(263.69,114.6) v2(263.69,113.9) v2(264.05,107.45) v2(264.75,107.45)
SIG00450:
  vias: v2(263.69,76.5) v2(263.69,75.8) v2(264.05,69.35) v2(264.75,69.35)
SIG00451: length 3.9
  BOTTOM w0.3: IC151.2 248.12,117.56 248.07,117.53 247.33,117.53 ; 246.97,117.53 245.78,117.53
  BOTTOM w0.45: 247.33,117.53 C158.2 246.97,117.53
SIG00452: length 3.9
  BOTTOM w0.3: 248.96,120.24 247.15,120.24 ; 246.97,120.22 245.78,120.22
  BOTTOM w0.45: C159.2 246.97,120.22
  BOTTOM w0.825: IC151.4 248.96,120.24
SIG00453: length 3.9
  BOTTOM w0.3: 246.97,79.42 245.78,79.42 ; IC201.2 248.12,79.47 248.07,79.42 247.33,79.42
  BOTTOM w0.45: 247.33,79.42 C208.2 246.97,79.42
SIG00460: length 3.9
  BOTTOM w0.3: 248.96,82.14 247.15,82.14 ; 246.97,82.12 245.78,82.12
  BOTTOM w0.45: C209.2 246.97,82.12
  BOTTOM w0.825: IC201.4 248.96,82.14
SIG00510: length 3
  TOP w0.3: 252.8,8.03 252.8,8.65 253.15,9 253.78,9 ; 251.78,7.97 R277.2
  TOP w0.45: R277.2 252.8,8.03 ; R282.1 251.78,7.97
SIG00511: length 20.9
  TOP w0.3: v2(268.15,2.2) 261.65,2.2 260.05,3.8 256.75,3.8 255.8,4.75 255.8,7.83 R278.1
  BOTTOM w0.3: 265.6,2.2 266.65,2.2 ; 266.83,2.17 268.15,2.17
  BOTTOM w0.45: R279.1 266.83,2.17 ; R280.2 265.6,2.2
SIG00513: length 7.9
  TOP w0.3: v2(262.7,8.3) 265.1,10.7 R254.2 266.1,11.62
  TOP w0.45: R253.2 266.1,11.62
  BOTTOM w0.3: v2(262.7,8.3) 262.12,7.72 261.15,7.72
  BOTTOM w0.4: 260.56,7.72 261.15,7.72
SIG00514: length 7.2
  TOP w0.3: v2(263.4,7.6) 264.3,8.5 R256.2 266.1,9.42
  TOP w0.45: R255.2 266.1,9.42
  BOTTOM w0.3: 261.32,7.08 262.88,7.08 v2(263.4,7.6)
  BOTTOM w0.4: IC251.7 261.32,7.08
SIG00515: length 6.1
  TOP w0.3: R259.2 265.3,5.2 v2(264.3,6.2)
  BOTTOM w0.3: v2(264.3,6.2) 263.88,5.78 261.32,5.78
  BOTTOM w0.4: IC251.9 261.32,5.78
SIG00516: length 7.2
  TOP w0.3: 266.1,7.22 R258.2 v2(265.3,6.3)
  TOP w0.45: R257.2 266.1,7.22
  BOTTOM w0.3: v2(265.3,6.3) 264.5,7.1 264.1,7.1 263.43,6.42 261.32,6.42
  BOTTOM w0.4: 260.56,6.42 261.32,6.42
SIG00517: length 4.9
  BOTTOM w0.3: 263.03,2.2 262.1,2.2 ; R281.2 261.52,2.23 260.56,3.19 260.56,3.73 ; 264.4,2.2 263.2,2.2
  BOTTOM w0.4: 263.2,2.2 263.03,2.2
  BOTTOM w0.45: R280.1 264.4,2.2
SIG00518: length 4.8
  BOTTOM w0.3: 262.7,4.95 262.02,4.95 261.85,5.12 261.16,5.12 ; 262.87,4.95 R265.1 ; 264.18,4.77 R263.1
  BOTTOM w0.4: IC251.10 261.16,5.12 ; 262.7,4.95 262.87,4.95
  BOTTOM w0.45: R265.1 264.18,4.77
SIG00519: length 7
  BOTTOM w0.3: IC251.4 263.7,9.03 264.1,9.43 265.06,9.43 ; C257.2 265.2,8.68 265.48,8.4 265.48,7.48
  BOTTOM w0.45: C257.2 265.06,9.43 ; 265.48,7.3 265.48,7.48
SIG00520: length 1.7
  BOTTOM w0.3: 268.78,12.03 270.3,12.03
  BOTTOM w0.45: R288.2 268.78,12.03
SIG00522: length 2.2
  BOTTOM w0.3: 271.9,10.12 R292.1
  BOTTOM w0.8: C258.2 271.9,10.12
SIG00525: length 4.5
  BOTTOM w0.3: IC251.11 259.12,4.47 257.82,3.17 257.82,2.17
  BOTTOM w0.45: R261.2 257.82,2.17
SIG00526:
  vias: v2(252.9,5.65)
SIG00527: length 2.2
  BOTTOM w0.3: 251.82,1.78 251.82,2.7 ; 251.82,2.88 251.82,3.8
  BOTTOM w0.45: 251.82,2.7 251.82,2.88 ; R268.1 251.82,1.78
SIG00528: length 12.2
  TOP w0.3: v2(254.75,2.55) 253.75,3.55 251.85,3.55 251.57,3.83 R274.1 250.69,4.7 ; 250.53,4.52 R275.2 ; 250.53,3.42 R270.1
  TOP w0.45: 250.69,4.7 R271.2 250.53,4.52 ; R275.2 250.53,3.42
  BOTTOM w0.3: IC251.14 255.88,4.47 256.25,4.1 256.25,3.05 255.75,2.55 v2(254.75,2.55)
SIG00772: length 2.2
  BOTTOM w0.3: 237.3,3.22 R365.2 ; 237.48,2.3 R364.1
  BOTTOM w0.45: R365.2 237.48,2.3 ; R363.1 237.3,3.22
SIG00774: length 4.5
  BOTTOM w0.3: 233.74,5.09 234.31,5.09 234.65,4.75 234.65,3.9 235.15,3.4 R363.2
  BOTTOM w0.55: 233.12,5.09 233.74,5.09
SIG00777: length 4.6
  BOTTOM w0.3: 233.94,8.9 235.25,8.9 236.45,7.7 R354.2
  BOTTOM w0.55: 233.12,8.9 233.94,8.9
SIG00781: length 3.8
  BOTTOM w0.3: 239.42,3.45 R361.1 ; 239.25,3.45 238.57,3.45 238.4,3.62 238.4,4.1 237.95,4.55 R360.1
  BOTTOM w0.4: 239.25,3.45 239.42,3.45
SIG00783: length 4.6
  BOTTOM w0.3: R357.2 236.05,5.75 235.7,6.1 235.7,6.9 234.97,7.63 233.88,7.63
  BOTTOM w0.55: 233.12,7.63 233.88,7.63
SIG00791: length 4.4
  BOTTOM w0.3: 233.74,6.37 234.28,6.37 235.35,5.3 235.35,4.8 235.6,4.55 R360.2
  BOTTOM w0.55: 233.12,6.37 233.74,6.37
SIG00799: length 1.7
  TOP w0.3: R351.2 235.5,3.3 235.47,3.33 234.75,3.33
  TOP w0.6: IC303.4 234.75,3.33
SIG00820: length 3.9
  BOTTOM w0.3: 182.45,91.2 R421.2
SIG00823: length 3
  BOTTOM w0.3: 237.7,13.3 238.8,13.3 ; 238.97,13.3 240.53,13.3
  BOTTOM w0.4: 238.8,13.3 238.97,13.3
  BOTTOM w0.45: R454.1 237.7,13.3
SIG00826: length 8.8
  BOTTOM w0.3: 244.32,13.32 245.12,13.32 245.3,13.5 246.28,13.5 246.28,12.1 245.49,11.31 243.29,11.31 ; 244.08,13.32 242.84,13.32
  BOTTOM w0.45: 244.08,13.32 244.32,13.32
  BOTTOM w0.825: 242.68,11.31 243.29,11.31
SIG00839: length 1.8
  TOP w0.3: 185.45,50.48 186.38,51.4 R416.2
SIG00847: length 18
  TOP w0.3: R403.1 207.07,18.18 203.81,21.45
  CONDUCTIVE3 w0.3: v2(198.8,16.9) 198.8,12.7 202.35,9.15 v2(204.7,9.15)
  BOTTOM w0.3: R407.2 205.2,9 205.05,9.15 v2(204.7,9.15)
SIG00848: length 1
  BOTTOM w0.3: 213.69,8.45 R413.1
  BOTTOM w0.45: C407.2 213.69,8.45
SIG00849: length 3
  BOTTOM w0.3: 210.32,12.98 211.55,12.98 ; 211.71,12.98 212.64,12.98
  BOTTOM w0.37: 211.55,12.98 211.71,12.98
  BOTTOM w0.65: IC401.2 210.32,12.98
SIG00851: length 10
  TOP w0.3: DP402.1 205.15,12.2 203.35,10.4 v2(202.6,10.4)
  BOTTOM w0.3: v2(202.6,10.4) 204.19,10.4 ; R407.1 206.57,9.62 205.75,10.45 204.24,10.45
SIG00854: length 2
  BOTTOM w0.3: IC401.3 210.91,11.71 R412.2
SIG00856: length 3.1
  TOP w0.3: v2(211.1,15.25) 210.25,14.4 DP401.1
SIG00859: length 38
  TOP w0.5: T401.5 215.5,19.65 211.95,23.2 211.95,37.65 209.09,40.51 D403.A
SIG00861: length 0.9
  BOTTOM w0.3: 212.65,12.01 R411.2
  BOTTOM w0.45: R410.1 212.65,12.01
SIG00863: length 6.9
  CONDUCTIVE3 w0.5: v2(202.55,11.7) 202.55,15.65 v2(204.65,17.75)
SIG00864: length 4.4
  TOP w0.3: R403.2 208.89,18.41 208.89,21.45
SIG007100: length 2.9
  BOTTOM w0.3: 126.58,7.78 127.95,7.78 ; 125.28,7.78 126.4,7.78
  BOTTOM w0.45: 125.1,7.78 125.28,7.78 ; 126.4,7.78 126.58,7.78
SIG007101: length 2.4
  TOP w0.3: 225.18,3.21 225.18,2.12 224.95,1.9 R317.2
  TOP w0.6: IC303.3 225.18,3.21
SIG007102: length 4.2
  BOTTOM w0.3: 135.68,11.9 134.33,11.9 134.23,11.87 134.19,11.84 133.06,10.71 133.01,10.62 133,10.57 133,9.8
  BOTTOM w0.4: D304.A 133,9.8
SIG007103: length 4.7
  TOP w0.3: 223.05,5.59 223.05,4.3 222.85,4.1 Q301.D ; 224.54,5.87 223,5.87
  TOP w0.6: IC303.1 224.54,5.87
  TOP w0.83: R316.1 223.05,5.59
SIG007105: length 2.2
  TOP w0.3: 237.03,2.27 238.05,2.27 ; 236.85,3.27 236.85,2.42
  TOP w0.45: 236.85,2.42 236.85,2.27 237.03,2.27
SIG007106: length 2.2
  BOTTOM w0.3: 127.17,3.16 127.17,4.1 R307.2
  BOTTOM w0.55: 127.17,3.1 127.17,3.16
SIG007112:
  vias: v2(209.5,3.7)
SIG007115: length 43.3
  TOP w0.3: R313.2 217.38,6.6 217.46,6.64 v2(218.12,7.3)
  CONDUCTIVE3 w0.3: v2(228.75,43.75) 228.75,16.25 219.8,7.3 v2(218.12,7.3)
SIG007116: length 2.6
  TOP w0.3: IC302.1 215.43,3.33 215.1,3 C308.2 214.68,3.92
  TOP w0.45: C307.2 214.68,3.92
SIG007118: length 1.7
  TOP w0.3: 238.64,3.65 R353.1
  TOP w0.5: Q351.D 238.64,3.65
SIG007123: length 5.8
  BOTTOM w0.3: 120.67,10.4 120.67,9.03 121.92,7.78 122.7,7.78 ; 126.48,5.83 IC301.5
  BOTTOM w0.45: R307.1 126.48,5.83
  BOTTOM w0.55: D302.C 120.67,10.4
  vias: v2(125.2,6.2)
SIG007124: length 2.9
  TOP w0.3: 220.1,4 R314.1 ; 221.13,3.8 220.1,3.8
  TOP w0.4: Q301.G 221.13,3.8
  TOP w0.45: R315.2 220.1,4
SIG007125: length 81.9
  CONDUCTIVE4 w0.3: v2(207.8,7.2) 203.55,2.95 194.5,2.95 192.55,1 161.85,1 159.5,3.35 151.9,3.35 151.25,2.7 142.6,2.7 141.85,1.95 139.6,1.95 137.25,4.3 135.05,4.3 v2(133.4,2.65)
  BOTTOM w0.3: 131.9,2.65 v2(133.4,2.65)
  BOTTOM w0.5: Q302.D 131.9,2.65
SIG007126: length 2.8
  TOP w0.3: 122.3,6.33 R320.1 ; 122.3,7.79 D305.A
  TOP w0.4: D305.A 122.3,6.33
  TOP w0.45: R321.2 122.3,7.79
SIGN254: length 2.1
  TOP w0.3: 157.73,48.5 159.18,48.5
  TOP w0.55: D66.A 157.73,48.5
SIGN255: length 2.1
  TOP w0.3: 136.27,47.7 134.82,47.7
  TOP w0.55: D61.A 136.27,47.7
SIGN266: length 1.1
  TOP w0.3: 152.93,54.87 R64.2
  TOP w0.45: C81.2 152.93,54.87
SIGN267: length 1.1
  TOP w0.3: 123.83,49.72 R56.2
  TOP w0.45: C82.2 123.83,49.72
SS/EN: length 32.2
  TOP w0.3: v2(242.8,6.65) 242.8,4.7 241.75,3.65 241.13,3.65
  TOP w0.45: R353.2 241.13,3.65
  CONDUCTIVE3 w0.3: v2(255.65,14.35) 253.2,14.35 251.7,12.85 251.7,10 247.9,6.2 243.25,6.2 v2(242.8,6.65)
  BOTTOM w0.3: v2(255.65,14.35) R252.2 ; 255.83,12.4 257.1,12.4 258.3,11.2 258.3,8.88 258.8,8.38 IC251.5 ; 255.65,13.32 C251.2
  BOTTOM w0.45: C251.2 255.83,12.4 ; R252.2 255.65,13.32
VREF_PSFB: length 4.8
  TOP w0.3: 251.55,2.5 v2(252.7,2.5)
  TOP w0.45: R270.2 251.55,2.5
  CONDUCTIVE3 w0.3: v2(266.1,3.85) 264.88,3.85 ; v2(261.9,11.1) 261.9,9.9 ; v2(252.7,2.5) 253.45,3.25

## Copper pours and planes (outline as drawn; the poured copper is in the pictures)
P48V on TOP: 295.15,24.85 295.04,24.89 295,25 295,30.85 294.5,31.35 290.3,31.35 290.24,31.36 290.19,31.39 288.22,33.37 288.19,33.42 288.18,33.48 288.18,36.15 287.95,36.68 287.92,36.76 287.91,36.84 287.91,37.01 288.32,37.42 288.74,37.01 288.74,36.84 288.73,36.76 288.7,36.68 288.48,36.15 288.48,33.54 290.36,31.65 294.5,31.65 295,32.15 295,36.34 295.01,36.4 295.04,36.44 302.26,43.66 302.3,43.69 302.36,43.7 317.8,43.7 317.91,43.66 317.95,43.55 317.95,25 317.91,24.89 317.8,24.85
P48V on BOTTOM: 287.3,25.5 287.19,25.54 287.15,25.65 287.15,27.35 287.19,27.46 287.3,27.5 289.3,27.5 289.41,27.46 289.45,27.35 289.45,25.65 289.41,25.54 289.3,25.5
P48V on BOTTOM: 301.2,6.8 301.09,6.84 301.05,6.95 301.05,9.15 301.09,9.25 301.2,9.3 301.9,9.3 302.01,9.25 302.05,9.15 302.05,6.95 302.01,6.84 301.9,6.8
P48V on BOTTOM: 295.15,24.85 295.04,24.89 295,25 295,37.39 295.01,37.45 295.04,37.49 301.21,43.66 301.25,43.69 301.31,43.7 317.8,43.7 317.91,43.66 317.95,43.55 317.95,25 317.91,24.89 317.8,24.85 317.52,24.85 317.42,24.89 317.38,25 317.38,25.57 317.25,25.88 316.95,26 315.85,26 315.55,25.88 315.43,25.57 315.43,25 315.38,24.89 315.27,24.85 315.02,24.85 314.92,24.89 314.88,25 314.88,25.57 314.75,25.88 314.45,26 313.35,26 313.05,25.88 312.93,25.57 312.93,25 312.88,24.89 312.77,24.85
VCC5R0_1 on TOP: 146.85,106.15 146.74,106.19 146.7,106.3 146.7,108.05 146.66,108.1 146.65,108.16 146.65,110.25 145.79,111.11 145.76,111.15 145.75,111.21 145.75,113.15 145.79,113.26 145.9,113.3 146.2,113.3 146.31,113.26 146.35,113.15 146.35,111.55 147.31,110.59 147.34,110.55 147.35,110.49 147.35,108.65 147.56,108.44 147.59,108.4 147.6,108.34 147.6,106.3 147.56,106.19 147.45,106.15
VCC12R0_1 on TOP: outline of 83 points within 201.99,3.75 220.32,10.7
VCC12R0_1 on TOP: 153.16,43.6 153.1,43.61 153.06,43.64 152.94,43.76 152.91,43.8 152.9,43.86 152.9,44.34 152.91,44.4 152.94,44.44 153.66,45.16 153.7,45.19 153.76,45.2 154.35,45.2 154.46,45.16 154.5,45.05 154.5,43.75 154.46,43.64 154.35,43.6
VCC12R0_1 on TOP: 122.1,2.9 121.99,2.94 121.95,3.05 121.95,4.45 121.99,4.56 122.1,4.6 122.65,4.6 122.76,4.56 122.8,4.45 122.8,3.05 122.76,2.94 122.65,2.9
VCC12R0_1 on BOTTOM: 149.26,103.15 149.2,103.16 149.16,103.19 148.99,103.36 148.96,103.4 148.95,103.46 148.95,103.69 148.96,103.75 148.99,103.79 149.01,103.81 149.05,103.84 149.11,103.85 149.34,103.85 149.4,103.84 149.44,103.81 149.5,103.75 149.9,103.75 152.75,106.6 152.75,111.65 152.77,111.74 152.82,111.83 157.65,116.65 157.65,118.75 157.61,118.8 157.6,118.86 157.6,119.15 157.64,119.26 157.75,119.3 158.05,119.3 158.16,119.26 158.2,119.15 158.2,118.86 158.19,118.8 158.16,118.76 158.15,116.55 158.13,116.46 158.08,116.37 153.25,111.55 153.25,106.5 153.23,106.4 153.18,106.32 150.18,103.32 150.1,103.27 150,103.25 149.5,103.25 149.44,103.19 149.4,103.16 149.34,103.15
